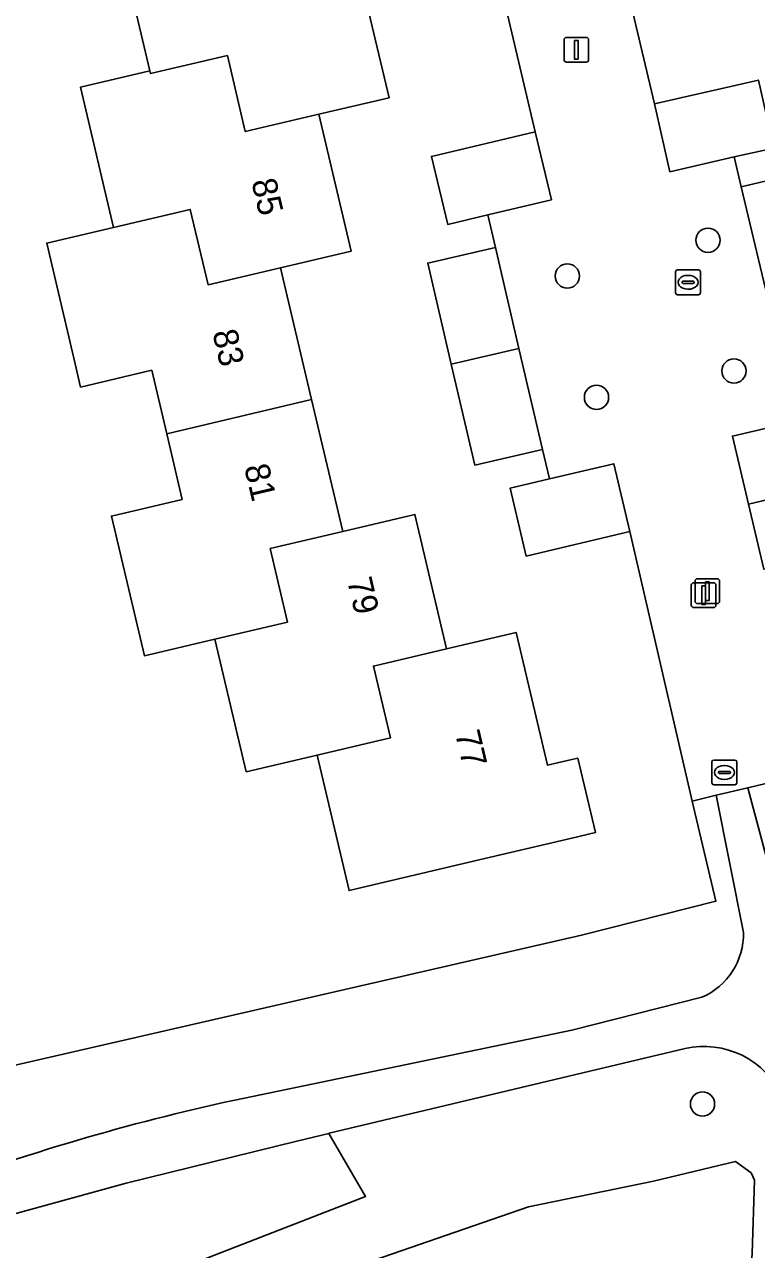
# Model space of a CAD drawing. Extents: x 158031 to 159244, y 380104 to 381214.
# Drawn here: x 158977.93 to 159007.45, y 380438.41 to 380487.85 of the extents above; entities that cross this region are included whole.
import ezdxf

# ---------------------------------------------------------------- set-up
doc = ezdxf.new("R2010")
doc.units = 0
for name, color, linetype in [('IMGEO_Boom', 7, 'Continuous'), ('IMGEO_Brandkraan', 7, 'Continuous'), ('IMGEO_Erf', 7, 'Continuous'), ('IMGEO_Groenvoorziening', 7, 'Continuous'), ('IMGEO_Kolk', 7, 'Continuous'), ('IMGEO_Lichtmast', 7, 'Continuous'), ('IMGEO_Pand', 7, 'Continuous'), ('IMGEO_Pand_nummerreeks', 7, 'Continuous'), ('IMGEO_Voetpad_halfverhard', 7, 'Continuous'), ('IMGEO_Voetpad_open', 7, 'Continuous'), ('IMGEO_Waterloop', 7, 'Continuous')]:
    doc.layers.add(name, color=color, linetype=linetype)

msp = doc.modelspace()

# ---------------------------------------------------------------- linework, layer by layer
at = {"layer": 'IMGEO_Boom'}
for centre in [(159005.494, 380479.143), (158999.819, 380477.698), (159006.538, 380473.867), (159000.996, 380472.803), (159005.272, 380444.286)]:
    msp.add_circle(centre, 0.489, dxfattribs=at)
at = {"layer": 'IMGEO_Brandkraan'}
for p, q in [((159005.653, 380457.241), (159005.653, 380458.093)), ((159005.728, 380458.167), (159006.58, 380458.167)), ((159006.141, 380457.947), (159006.166, 380457.947)), ((159006.654, 380458.093), (159006.654, 380457.241)), ((159005.912, 380457.661), (159005.912, 380457.673)), ((159006.35, 380457.624), (159005.952, 380457.624)), ((159005.955, 380457.71), (159006.353, 380457.71)), ((159006.164, 380457.387), (159006.139, 380457.387)), ((159006.396, 380457.673), (159006.396, 380457.661)), ((159006.58, 380457.167), (159005.728, 380457.167))]:
    msp.add_line(p, q, dxfattribs=at)
for points in [[(159005.653, 380457.241), (159005.653, 380458.093)], [(159005.728, 380458.167), (159006.58, 380458.167)], [(159006.654, 380458.093), (159006.654, 380457.241)], [(159006.58, 380457.167), (159005.728, 380457.167)]]:
    msp.add_lwpolyline(points, dxfattribs=at)
for centre, radius, start, end in [((159005.73, 380458.091), 0.0765, 91.552, 178.448), ((159005.73, 380458.091), 0.0765, 91.552, 178.448), ((159006.578, 380458.091), 0.0765, 1.552, 88.448), ((159006.578, 380458.091), 0.0765, 1.552, 88.448), ((159005.952, 380457.67), 0.0403, 85.8775, 175.7526), ((159005.949, 380457.66), 0.0366, 178.938, 274.7102), ((159006.353, 380457.667), 0.043, 264.8664, 352.4533), ((159006.357, 380457.672), 0.0386, 1.7309, 96.639), ((159005.73, 380457.243), 0.0765, 181.552, 268.448), ((159005.73, 380457.243), 0.0765, 181.552, 268.448), ((159006.578, 380457.243), 0.0765, 271.552, 358.448), ((159006.578, 380457.243), 0.0765, 271.552, 358.448)]:
    msp.add_arc(centre, radius, start, end, dxfattribs=at)
for centre, major_axis, ratio, start_param, end_param in [((159006.14, 380457.667), (-0.387, 0.002), 0.722429, 4.712389, 7.853982), ((159006.165, 380457.667), (-0.39, 0.002), 0.717154, 1.570796, 4.712389)]:
    msp.add_ellipse(centre, major_axis=major_axis, ratio=ratio, start_param=start_param, end_param=end_param, dxfattribs=at)
at = {"layer": 'IMGEO_Erf'}
for points in [[(159001.275, 380493.342), (159003.333, 380484.648), (159007.525, 380485.605), (159008.151, 380482.861), (159006.55, 380482.505), (159006.835, 380481.298), (159009.56, 380481.941), (159010.532, 380477.819), (159011.505, 380473.697), (159008.78, 380473.054), (159009.064, 380471.847), (159010.658, 380472.234), (159011.312, 380469.49), (159007.13, 380468.492), (159007.746, 380465.864), (159008.33, 380466.001), (159009.06, 380462.885), (159008.476, 380462.748), (159008.748, 380461.587), (159009.334, 380461.717), (159010.252, 380457.799), (159011.184, 380453.562), (159013.381, 380446.231)], [(158883.466, 380431.148), (158973.949, 380452.625), (158975.667, 380445.423), (159000.386, 380451.105), (159005.809, 380452.471), (159004.857, 380456.513), (159002.342, 380467.386), (158998.158, 380466.394), (158997.509, 380469.134), (158999.096, 380469.51), (158998.813, 380470.7), (158996.086, 380470.066), (158995.139, 380474.143), (158994.191, 380478.219), (158996.918, 380478.853), (158996.608, 380480.167), (158994.994, 380479.778), (158994.341, 380482.524), (158998.524, 380483.52), (158996.573, 380491.798)], [(158991.335, 380490.375), (158992.633, 380484.891), (158989.803, 380484.225), (158991.104, 380478.704), (158988.255, 380478.033), (158989.509, 380472.712), (158990.763, 380467.389), (158993.676, 380468.075), (158994.953, 380462.655), (158997.756, 380463.316), (158999.02, 380457.953), (159000, 380458.183), (159000.242, 380458.24), (159000.958, 380455.243), (159000, 380455.017), (158996.092, 380454.094), (158991.019, 380452.895), (158989.73, 380458.366), (158986.87, 380457.692), (158985.609, 380463.043), (158982.762, 380462.372), (158981.433, 380468.013), (158984.285, 380468.685), (158983.662, 380471.331), (158983.058, 380473.893), (158980.191, 380473.218), (158979.969, 380474.16), (158978.823, 380479.026), (158981.523, 380479.662), (158980.188, 380485.323), (158982.986, 380485.983), (158981.696, 380491.447)]]:
    msp.add_lwpolyline(points, dxfattribs=at)
at = {"layer": 'IMGEO_Groenvoorziening'}
for points in [[(159012.831, 380445.978), (159010.603, 380453.411), (159009.667, 380457.666), (159007.094, 380457.049), (159010.154, 380445.614), (159014.014, 380438.354), (159015.641, 380435.392), (159017.119, 380434.731), (159021.275, 380434.438), (159025.136, 380434.718), (159028.573, 380435.153), (159032.223, 380436.053), (159036.326, 380437.058), (159038.675, 380438.351), (159044.663, 380441.807), (159049.514, 380444.606), (159049.815, 380444.964), (159050.396, 380446.047)], [(159006.925, 380451.21), (159005.828, 380456.746), (159004.857, 380456.513), (159005.809, 380452.471), (159000.386, 380451.105), (158975.667, 380445.423), (158973.949, 380452.625), (158883.466, 380431.148), (158888.059, 380413.158), (158888.945, 380411.442), (158890.833, 380408.861), (158893.84, 380407.549), (158904.192, 380408.639), (158913.221, 380409.146), (158921.261, 380409.922), (158925.707, 380410.919), (158927.74, 380411.665), (158930.409, 380413.109), (158934.592, 380416.844), (158944.855, 380424.497)], [(158986.405, 380444.446), (159000, 380447.269), (159005.246, 380448.592)], [(159013.064, 380435.949), (159008.349, 380444.859), (159008.192, 380445.108), (159008.015, 380445.343), (159007.818, 380445.562), (159007.604, 380445.764), (159007.373, 380445.947), (159007.127, 380446.109), (159006.869, 380446.251), (159006.6, 380446.37), (159006.321, 380446.465), (159006.036, 380446.537), (159005.745, 380446.585), (159005.452, 380446.607), (159005.157, 380446.605), (159004.864, 380446.578), (159004.574, 380446.526), (158990.215, 380443.104), (158990.2, 380443.1), (158991.681, 380440.555), (158985.343, 380438.098), (158978.344, 380435.135), (158969.567, 380430.941)], [(158952.676, 380417.201), (158968.213, 380426.669), (158979.606, 380432.885), (158990.555, 380437.472), (158998.25, 380440.135), (159003.296, 380441.176), (159006.601, 380441.964), (159007.229, 380441.511), (159007.365, 380441.211), (159007.277, 380438.258), (159007.127, 380436.436), (159004.168, 380434.81), (158995.29, 380432.293), (158989.52, 380427.706), (158976.203, 380417.941), (158965.993, 380410.838), (158961.508, 380407.397), (158963.032, 380404.646), (158972.708, 380412.337), (158980.033, 380418.504), (158989.223, 380424.225)]]:
    msp.add_lwpolyline(points, dxfattribs=at)
msp.add_lwpolyline([(158985.343, 380438.098), (158991.681, 380440.555), (158990.2, 380443.1), (158988.907, 380442.792), (158982.026, 380441.092), (158976.694, 380439.627), (158973.372, 380438.686), (158967.135, 380435.554), (158967.125, 380435.549), (158969.567, 380430.941), (158978.344, 380435.135)], close=True, dxfattribs=at)
for centre, radius, start, end in [((159004.129, 380451.156), 2.796, 293.5405, 1.113), ((159005.819, 380355.352), 91.184, 102.29293, 110.55946)]:
    msp.add_arc(centre, radius, start, end, dxfattribs=at)
at = {"layer": 'IMGEO_Kolk'}
for p, q in [((159004.188, 380477.019), (159004.188, 380477.871)), ((159004.263, 380477.945), (159005.115, 380477.945)), ((159004.676, 380477.725), (159004.701, 380477.725)), ((159005.189, 380477.871), (159005.189, 380477.019)), ((159004.447, 380477.439), (159004.447, 380477.451)), ((159004.885, 380477.402), (159004.487, 380477.402)), ((159004.49, 380477.488), (159004.888, 380477.488)), ((159004.699, 380477.165), (159004.674, 380477.165)), ((159004.931, 380477.451), (159004.931, 380477.439)), ((159005.115, 380476.945), (159004.263, 380476.945))]:
    msp.add_line(p, q, dxfattribs=at)
for points in [[(159004.188, 380477.019), (159004.188, 380477.871)], [(159004.263, 380477.945), (159005.115, 380477.945)], [(159005.189, 380477.871), (159005.189, 380477.019)], [(159005.115, 380476.945), (159004.263, 380476.945)]]:
    msp.add_lwpolyline(points, dxfattribs=at)
for centre, radius, start, end in [((159004.265, 380477.869), 0.0765, 91.552, 178.448), ((159004.265, 380477.869), 0.0765, 91.552, 178.448), ((159005.113, 380477.869), 0.0765, 1.552, 88.448), ((159005.113, 380477.869), 0.0765, 1.552, 88.448), ((159004.487, 380477.448), 0.0403, 85.8775, 175.7526), ((159004.484, 380477.438), 0.0366, 178.938, 274.7102), ((159004.888, 380477.445), 0.043, 264.8664, 352.4533), ((159004.892, 380477.45), 0.0386, 1.7309, 96.639), ((159004.265, 380477.021), 0.0765, 181.552, 268.448), ((159004.265, 380477.021), 0.0765, 181.552, 268.448), ((159005.113, 380477.021), 0.0765, 271.552, 358.448), ((159005.113, 380477.021), 0.0765, 271.552, 358.448)]:
    msp.add_arc(centre, radius, start, end, dxfattribs=at)
for centre, major_axis, ratio, start_param, end_param in [((159004.675, 380477.445), (-0.387, 0.002), 0.722429, 4.712389, 7.853982), ((159004.7, 380477.445), (-0.39, 0.002), 0.717154, 1.570796, 4.712389)]:
    msp.add_ellipse(centre, major_axis=major_axis, ratio=ratio, start_param=start_param, end_param=end_param, dxfattribs=at)
at = {"layer": 'IMGEO_Lichtmast'}
for p, q in [((158999.686, 380486.43), (158999.686, 380487.23)), ((158999.686, 380487.23), (158999.686, 380486.43)), ((158999.786, 380487.33), (159000.576, 380487.33)), ((159000.576, 380487.33), (158999.786, 380487.33)), ((159000.676, 380487.23), (159000.676, 380486.43)), ((159000.676, 380486.43), (159000.676, 380487.23)), ((159000.576, 380486.33), (158999.786, 380486.33)), ((158999.786, 380486.33), (159000.576, 380486.33)), ((159004.92, 380465.319), (159005.71, 380465.319)), ((159005.71, 380465.319), (159004.92, 380465.319)), ((159004.97, 380464.581), (159004.97, 380465.381)), ((159004.97, 380465.381), (159004.97, 380464.581)), ((159005.07, 380465.481), (159005.86, 380465.481)), ((159005.86, 380465.481), (159005.07, 380465.481)), ((159005.96, 380465.381), (159005.96, 380464.581)), ((159005.96, 380464.581), (159005.96, 380465.381)), ((159004.82, 380464.419), (159004.82, 380465.219)), ((159004.82, 380465.219), (159004.82, 380464.419)), ((159005.81, 380465.219), (159005.81, 380464.419)), ((159005.81, 380464.419), (159005.81, 380465.219)), ((159005.71, 380464.319), (159004.92, 380464.319)), ((159004.92, 380464.319), (159005.71, 380464.319)), ((159005.86, 380464.481), (159005.07, 380464.481)), ((159005.07, 380464.481), (159005.86, 380464.481))]:
    msp.add_line(p, q, dxfattribs=at)
for points in [[(159000.106, 380487.205), (159000.256, 380487.205), (159000.256, 380486.455), (159000.106, 380486.455), (159000.106, 380487.205)], [(159005.39, 380465.356), (159005.54, 380465.356), (159005.54, 380464.606), (159005.39, 380464.606), (159005.39, 380465.356)], [(159005.24, 380465.194), (159005.39, 380465.194), (159005.39, 380464.444), (159005.24, 380464.444), (159005.24, 380465.194)]]:
    msp.add_lwpolyline(points, dxfattribs=at)
for centre, start, end in [((158999.786, 380487.23), 90, 180), ((158999.786, 380487.23), 90, 180), ((159000.576, 380487.23), 0, 90), ((159000.576, 380487.23), 360, 90), ((158999.786, 380486.43), 180, 270), ((158999.786, 380486.43), 180, 270), ((159000.576, 380486.43), 270, 0), ((159000.576, 380486.43), 270, 0), ((159004.92, 380465.219), 90, 180), ((159004.92, 380465.219), 90, 180), ((159005.07, 380465.381), 90, 180), ((159005.07, 380465.381), 90, 180), ((159005.71, 380465.219), 0, 90), ((159005.71, 380465.219), 360, 90), ((159005.86, 380465.381), 0, 90), ((159005.86, 380465.381), 360, 90), ((159004.92, 380464.419), 180, 270), ((159004.92, 380464.419), 180, 270), ((159005.07, 380464.581), 180, 270), ((159005.07, 380464.581), 180, 270), ((159005.71, 380464.419), 270, 0), ((159005.71, 380464.419), 270, 0), ((159005.86, 380464.581), 270, 0), ((159005.86, 380464.581), 270, 0)]:
    msp.add_arc(centre, 0.1, start, end, dxfattribs=at)
at = {"layer": 'IMGEO_Pand'}
for points in [[(158989.803, 380484.225), (158992.633, 380484.891), (158991.335, 380490.375), (158992.609, 380490.676), (158992.566, 380490.857), (158991.859, 380493.844), (158981.696, 380491.447), (158982.986, 380485.983), (158983.013, 380485.865), (158986.111, 380486.595), (158986.834, 380483.526)], [(158988.255, 380478.033), (158991.104, 380478.704), (158989.803, 380484.225), (158986.834, 380483.526), (158986.111, 380486.595), (158983.013, 380485.865), (158982.986, 380485.983), (158980.188, 380485.323), (158981.523, 380479.662), (158984.614, 380480.389), (158985.331, 380477.344)], [(159006.55, 380482.505), (159008.151, 380482.861), (159007.525, 380485.605), (159003.333, 380484.648), (159003.959, 380481.905)], [(158998.524, 380483.52), (158994.341, 380482.524), (158994.994, 380479.778), (158996.608, 380480.167), (158999.177, 380480.774)], [(159010.532, 380477.819), (159009.56, 380481.941), (159006.835, 380481.298), (159007.807, 380477.176)], [(158989.509, 380472.712), (158988.255, 380478.033), (158985.331, 380477.344), (158984.614, 380480.389), (158981.523, 380479.662), (158978.823, 380479.026), (158979.969, 380474.16), (158980.191, 380473.218), (158983.058, 380473.893), (158983.662, 380471.331)], [(158997.866, 380474.777), (158996.918, 380478.853), (158994.191, 380478.219), (158995.139, 380474.143)], [(158997.866, 380474.777), (158995.139, 380474.143), (158996.086, 380470.066), (158998.813, 380470.7)], [(158989.509, 380472.712), (158983.662, 380471.331), (158984.285, 380468.685), (158981.433, 380468.013), (158982.762, 380462.372), (158985.609, 380463.043), (158988.536, 380463.733), (158987.837, 380466.7), (158990.763, 380467.389)], [(159007.13, 380468.492), (159011.312, 380469.49), (159010.658, 380472.234), (159009.064, 380471.847), (159006.475, 380471.237)], [(159002.342, 380467.386), (159001.693, 380470.126), (158999.096, 380469.51), (158997.509, 380469.134), (158998.158, 380466.394)], [(158990.763, 380467.389), (158987.837, 380466.7), (158988.536, 380463.733), (158985.609, 380463.043), (158986.87, 380457.692), (158989.73, 380458.366), (158992.683, 380459.062), (158992, 380461.959), (158994.953, 380462.655), (158993.676, 380468.075)], [(158989.73, 380458.366), (158991.019, 380452.895), (158996.092, 380454.094), (159000, 380455.017), (159000.958, 380455.243), (159000.242, 380458.24), (159000, 380458.183), (158999.02, 380457.953), (158997.756, 380463.316), (158994.953, 380462.655), (158992, 380461.959), (158992.683, 380459.062)]]:
    msp.add_lwpolyline(points, close=True, dxfattribs=at)
at = {"layer": 'IMGEO_Voetpad_halfverhard'}
for points in [[(158953.412, 380394.217), (158959.059, 380397.328), (158966.434, 380402.774), (158972.919, 380409.555), (158977.497, 380413.606), (158981.185, 380416.314), (158988.906, 380421.731), (158992.767, 380423.69), (159000, 380426.451), (159010.319, 380430.447), (159010.453, 380430.483), (159018.142, 380431.922), (159017.119, 380434.731), (159015.641, 380435.392), (159014.014, 380438.354), (159010.154, 380445.614), (159007.094, 380457.049), (159005.828, 380456.746), (159006.925, 380451.21)], [(159005.246, 380448.592), (159000, 380447.269), (158986.405, 380444.446)], [(158976.694, 380439.627), (158982.026, 380441.092), (158988.907, 380442.792), (158990.2, 380443.1), (158990.215, 380443.104), (159004.574, 380446.526), (159004.864, 380446.578), (159005.157, 380446.605), (159005.452, 380446.607), (159005.745, 380446.585), (159006.036, 380446.537), (159006.321, 380446.465), (159006.6, 380446.37), (159006.869, 380446.251), (159007.127, 380446.109), (159007.373, 380445.947), (159007.604, 380445.764), (159007.818, 380445.562), (159008.015, 380445.343), (159008.192, 380445.108), (159008.349, 380444.859), (159013.064, 380435.949)]]:
    msp.add_lwpolyline(points, dxfattribs=at)
for centre, radius, start, end in [((159004.129, 380451.156), 2.796, 293.5405, 1.113), ((159005.819, 380355.352), 91.184, 102.29293, 110.55946)]:
    msp.add_arc(centre, radius, start, end, dxfattribs=at)
at = {"layer": 'IMGEO_Voetpad_open'}
for points in [[(159007.807, 380477.176), (159006.835, 380481.298), (159006.55, 380482.505), (159003.959, 380481.905), (159003.333, 380484.648), (159001.275, 380493.342)], [(158996.573, 380491.798), (158998.524, 380483.52), (158999.177, 380480.774), (158996.608, 380480.167), (158996.918, 380478.853), (158997.866, 380474.777), (158998.813, 380470.7), (158999.096, 380469.51), (159001.693, 380470.126), (159002.342, 380467.386), (159004.857, 380456.513), (159005.828, 380456.746), (159007.094, 380457.049), (159009.667, 380457.666)], [(159007.746, 380465.864), (159007.13, 380468.492), (159006.475, 380471.237), (159009.064, 380471.847)]]:
    msp.add_lwpolyline(points, dxfattribs=at)
at = {"layer": 'IMGEO_Waterloop'}
msp.add_lwpolyline([(159007.277, 380438.258), (159007.365, 380441.211), (159007.229, 380441.511), (159006.601, 380441.964), (159003.296, 380441.176), (158998.25, 380440.135), (158990.555, 380437.472), (158979.606, 380432.885), (158968.213, 380426.669), (158952.676, 380417.201), (158946.376, 380412.112), (158941.135, 380407.879), (158938.68, 380403.56), (158942.023, 380399.149), (158946.754, 380399.433), (158949.421, 380399.593), (158955.192, 380402.552), (158961.508, 380407.397), (158965.993, 380410.838), (158976.203, 380417.941), (158989.52, 380427.706), (158995.29, 380432.293), (159004.168, 380434.81), (159007.127, 380436.436)], close=True, dxfattribs=at)

# ---------------------------------------------------------------- texts
at = {"layer": 'IMGEO_Pand_nummerreeks'}
for s, rotation, p in [('85', 283.2596, (158987.072, 380481.517)), ('83', 283.2609, (158985.5, 380475.425)), ('81', 283.2561, (158986.78, 380469.994)), ('79', 283.2576, (158990.932, 380465.417)), ('77', 283.262, (158995.285, 380459.248))]:
    msp.add_text(s, height=1, rotation=rotation, dxfattribs=at).set_placement(p)

doc.saveas('drawing.dxf')
